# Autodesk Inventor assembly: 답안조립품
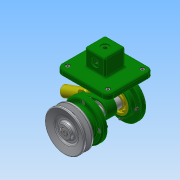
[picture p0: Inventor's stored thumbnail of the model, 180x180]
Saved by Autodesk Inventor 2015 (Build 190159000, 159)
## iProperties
Created: 2017-08
Part Number: 답안조립품
Document SubType Name: Assembly
Designer: owner
Author: owner
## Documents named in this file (16)
- C:\Users\owner\Desktop\470807V1008\답안조립품.iam
- C:\Users\owner\Desktop\470807V1008\1.본체.ipt
- C:\Users\owner\Desktop\470807V1008\뒤커버.ipt
- C:\Users\owner\Desktop\470807V1008\앞커버.ipt
- C:\Users\owner\Desktop\470807V1008\베어링 17 x 40 x 12.ipt
- C:\Users\owner\Desktop\470807V1008\링크.ipt
- C:\Users\owner\Desktop\470807V1008\슬라이더.ipt
- C:\Users\owner\Desktop\470807V1008\클레비스 핀 6 x 22.ipt
- 클레비스 핀 6 x 22.ipt
- C:\Users\owner\Desktop\470807V1008\편심축.ipt
- C:\Users\owner\Desktop\470807V1008\오일 실 17 30 8.ipt
- C:\Users\owner\Desktop\470807V1008\V-벨트풀리.ipt
- C:\Users\owner\Desktop\470807V1008\키 4 x 4 x 12.ipt
- C:\Users\owner\Desktop\470807V1008\볼트 M4 x 10.ipt
- C:\Users\owner\Desktop\470807V1008\덮개.ipt
- C:\Users\owner\Desktop\470807V1008\볼트 M4 x 8.ipt
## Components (2 placed, 2 different names)
1. 1.본체:1
2. V-벨트풀리:2 — 플러쉬:2, 각도:1
## Component patterns: 구성요소 패턴 1:2 (4 elements), 구성요소 패턴 1:3 (4 elements), 구성요소 패턴 1:4 (4 elements)
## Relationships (2: Flush 1, Angle 1)
- 플러쉬:2 [Flush]: V-벨트풀리:2
- 각도:1 [Angle]: V-벨트풀리:2
